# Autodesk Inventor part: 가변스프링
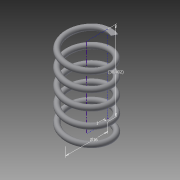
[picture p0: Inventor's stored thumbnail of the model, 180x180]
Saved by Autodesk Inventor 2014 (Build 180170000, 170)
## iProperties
Created: 2016-12
Part Number: 가변스프링
Material: Generic
Document SubType Name: Modeling
Designer: user
Density: 1 g/cm^3
Appearance: Default
Mass: 0.788979 g
Surface Area: 16.0181 cm^2
Volume: 0.788979 cm^3
Author: user
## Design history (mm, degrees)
sketch "Sketch1"
  geometry: L1 (0, 0)-(8, 0); L2 (8, 0)-(8, 30.402); L3 (8, 30.402)-(0, 30.402); L4 (0, 30.402)-(0, 0); C1 r 1 at (8, 0)
  constraints: 8 end point, 2 parallel, 1 centre point, 1 coincident, 1 horizontal, 1 perpendicular
  dimensions: "d0" = 16 diameter of L2 L4; "d1" = 30.40208 distance between parallel lines of L1 L3 (derived); "d2" = 1 radius of C1
coil "Coil1" pitch "d3" = 6; turns "d5" = 1; dims "d4" = 30.40208 (= d1), "d6" = 0, angle "d7" = 90 deg, angle "d8" = 90 deg, "d9" = 0, "d10" = 0
sketch "Sketch2"
  geometry: L1 (0, 7)-(0, 9) reference; 1 further point
  constraints: 1 vertical alignment
extrude "Extrusion1" cut sketch "Sketch2" distance "d11" = 10; taper "d12" = 0 deg
workplane "Work Plane1"
workplane "Work Plane2"
sketch "Sketch3"
  geometry: L1 (-2.861, 6.389)-(-3.679, 8.214) reference; 1 further point
  constraints: 1 other
extrude "Extrusion2" cut sketch "Sketch3" distance "d13" = 10; taper "d14" = 0 deg
body "Solid1"
node "Project Cut Edges1"
node "Project Cut Edges2"
